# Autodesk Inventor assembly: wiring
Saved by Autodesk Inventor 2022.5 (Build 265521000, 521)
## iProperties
Created: 2024-12
Part Number: wiring
Document SubType Name: Assembly
Designer: AdminForWorker
Title: wiring
Author: AdminForWorker
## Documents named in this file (4)
- c:\worker\convert-fusion-r05-cosv3\tmp\job-1\35\temp\files\545dca92-a972-481a-9197-dd1a1176500e\wiring.iam
- c:\worker\convert-fusion-r05-cosv3\tmp\job-1\35\temp\files\545dca92-a972-481a-9197-dd1a1176500e\rj45.ipt
- c:\worker\convert-fusion-r05-cosv3\tmp\job-1\35\temp\files\545dca92-a972-481a-9197-dd1a1176500e\magnetics.ipt
- c:\worker\convert-fusion-r05-cosv3\tmp\job-1\35\temp\files\545dca92-a972-481a-9197-dd1a1176500e\leads.ipt
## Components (3 placed, 3 different names)
1. rj45:1
2. magnetics:1
3. leads:1
